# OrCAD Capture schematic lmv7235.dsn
size A
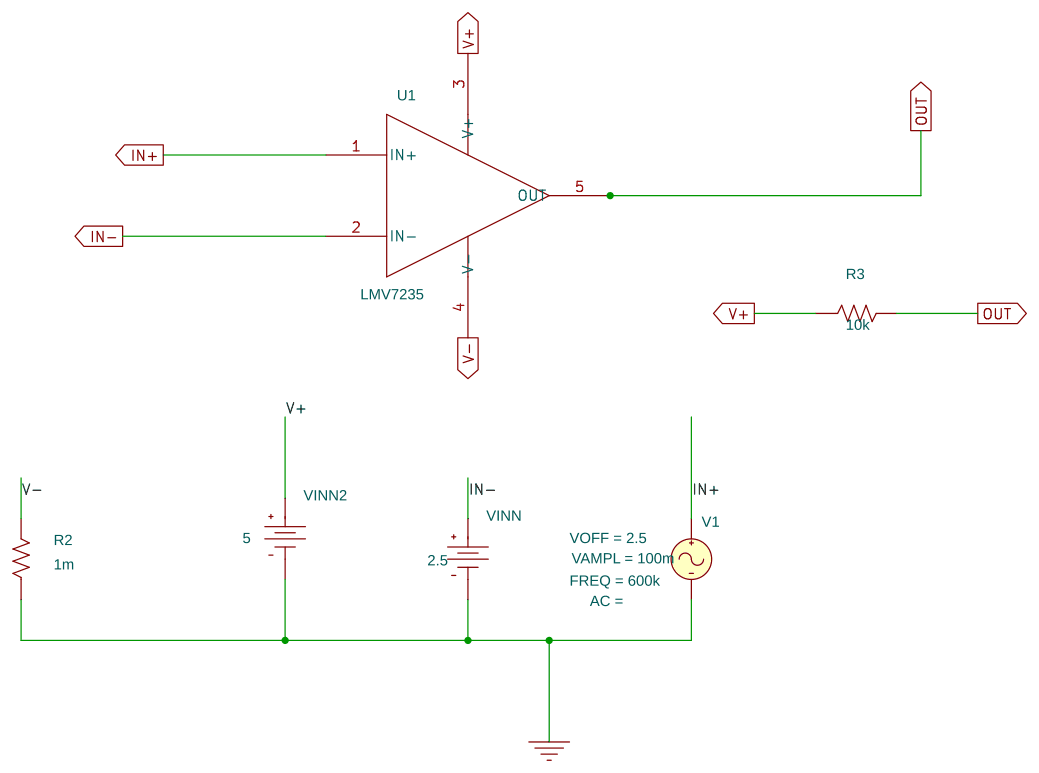
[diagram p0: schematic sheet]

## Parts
R2  1m  [AXRC05]
R3  10k  [AXRC05]
U1  LMV7235
V1  VSIN
VINN  VDC
VINN2  VDC

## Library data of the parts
R2 R3 = R
U1 = LMV7235_0
V1 = VSIN: FREQ: 600k; VAMPL: 100m; VOFF: 2.5
VINN = VDC: DC: 2.5
VINN2 = VDC: DC: 5

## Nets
0: R2.1 V1.2(-) VINN.1(-) VINN2.1(-)
IN+: U1.1(IN+) V1.1(+)
IN-: U1.2(IN-) VINN.0(+)
OUT: R3.2 U1.5(OUT)
V+: R3.1 U1.3(V+) VINN2.0(+)
V-: R2.2 U1.4(V-)
